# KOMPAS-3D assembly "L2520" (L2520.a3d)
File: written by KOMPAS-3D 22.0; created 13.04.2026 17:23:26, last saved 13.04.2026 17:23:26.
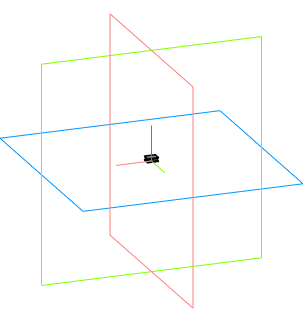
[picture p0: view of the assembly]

Document properties: Автор: Andrey; Полное имя файла: C:\Users\User1\Documents\L2520.a3d

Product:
- Component [detail]: LQH2HPN150MGRL  | qty 1  | source file: LQH2HPN150MGRL.m3d
- Part/product: L2520
    Комментарий: L2520

Referenced files in C:\Users\User1\Documents\: LQH2HPN150MGRL.m3d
